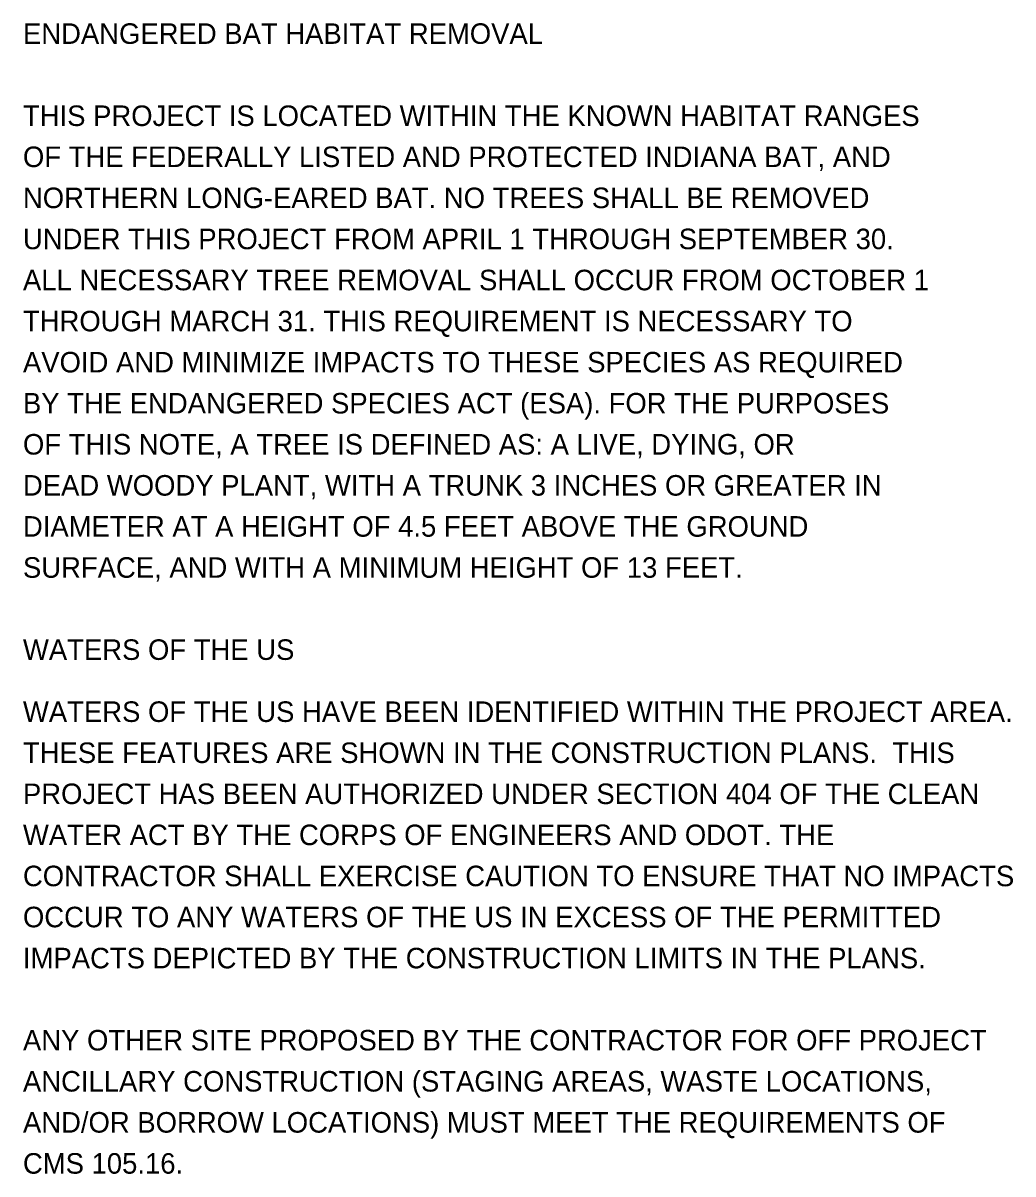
# Model space of a CAD drawing. Extents: x -286 to 93, y -30 to 99.
# Drawn here: x 55.4 to 62.16, y 31.61 to 39.46 of the extents above; entities that cross this region are included whole.
import ezdxf

# ---------------------------------------------------------------- set-up
doc = ezdxf.new("R2010")
doc.units = 0
doc.layers.add('SH_Text', color=7, linetype='Continuous')

msp = doc.modelspace()

# ---------------------------------------------------------------- texts
at = {"layer": 'SH_Text'}
for s, p in [('ENDANGERED BAT HABITAT REMOVAL', (55.4039, 39.3185)), ('THIS PROJECT IS LOCATED WITHIN THE KNOWN HABITAT RANGES', (55.4039, 38.7585)), ('OF THE FEDERALLY LISTED AND PROTECTED INDIANA BAT, AND', (55.4039, 38.4785)), ('NORTHERN LONG-EARED BAT. NO TREES SHALL BE REMOVED', (55.4039, 38.1985)), ('UNDER THIS PROJECT FROM APRIL 1 THROUGH SEPTEMBER 30.', (55.4039, 37.9185)), ('ALL NECESSARY TREE REMOVAL SHALL OCCUR FROM OCTOBER 1', (55.4039, 37.6385)), ('THROUGH MARCH 31. THIS REQUIREMENT IS NECESSARY TO', (55.4039, 37.3585)), ('AVOID AND MINIMIZE IMPACTS TO THESE SPECIES AS REQUIRED', (55.4039, 37.0785)), ('BY THE ENDANGERED SPECIES ACT (ESA). FOR THE PURPOSES', (55.4039, 36.7985)), ('OF THIS NOTE, A TREE IS DEFINED AS: A LIVE, DYING, OR', (55.4039, 36.5185)), ('DEAD WOODY PLANT, WITH A TRUNK 3 INCHES OR GREATER IN', (55.4039, 36.2385)), ('DIAMETER AT A HEIGHT OF 4.5 FEET ABOVE THE GROUND', (55.4039, 35.9585)), ('SURFACE, AND WITH A MINIMUM HEIGHT OF 13 FEET.', (55.4039, 35.6785)), ('WATERS OF THE US', (55.4039, 35.1185)), ('WATERS OF THE US HAVE BEEN IDENTIFIED WITHIN THE PROJECT AREA.  ', (55.4039, 34.6955)), ('THESE FEATURES ARE SHOWN IN THE CONSTRUCTION PLANS.  THIS ', (55.4039, 34.4155)), ('PROJECT HAS BEEN AUTHORIZED UNDER SECTION 404 OF THE CLEAN ', (55.4039, 34.1355)), ('WATER ACT BY THE CORPS OF ENGINEERS AND ODOT. THE ', (55.4039, 33.8555)), ('CONTRACTOR SHALL EXERCISE CAUTION TO ENSURE THAT NO IMPACTS ', (55.4039, 33.5755)), ('OCCUR TO ANY WATERS OF THE US IN EXCESS OF THE PERMITTED ', (55.4039, 33.2955)), ('IMPACTS DEPICTED BY THE CONSTRUCTION LIMITS IN THE PLANS.  ', (55.4039, 33.0155)), ('ANY OTHER SITE PROPOSED BY THE CONTRACTOR FOR OFF PROJECT ', (55.4039, 32.4555)), ('ANCILLARY CONSTRUCTION (STAGING AREAS, WASTE LOCATIONS, ', (55.4039, 32.1755)), ('AND/OR BORROW LOCATIONS) MUST MEET THE REQUIREMENTS OF ', (55.4039, 31.8956)), ('CMS 105.16.', (55.4039, 31.6156))]:
    msp.add_text(s, height=0.14, dxfattribs=at).set_placement(p)

doc.saveas('drawing.dxf')
